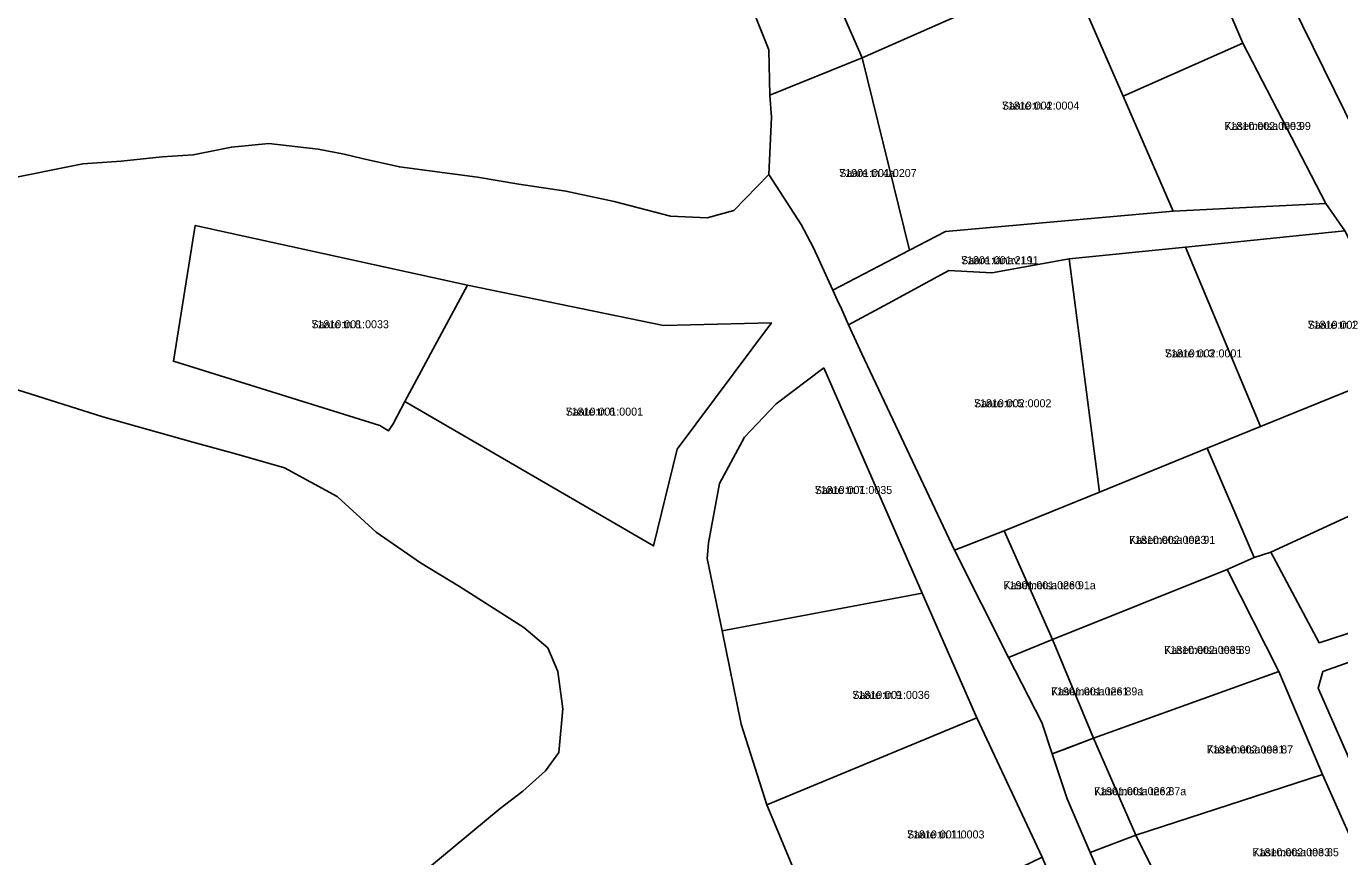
# Model space of a CAD drawing. Extents: x 529768 to 552006, y 6562269 to 6580975.
# Drawn here: x 537630.1 to 537876.3, y 6567349.9 to 6567505.6 of the extents above; entities that cross this region are included whole.
import ezdxf

# ---------------------------------------------------------------- set-up
doc = ezdxf.new("R2010")
doc.units = 0
for name, color, linetype in [('L_AADRESS', 7, 'Continuous'), ('PIIR', 7, 'Continuous'), ('TUNNUS', 7, 'Continuous')]:
    doc.layers.add(name, color=color, linetype=linetype)

msp = doc.modelspace()

# ---------------------------------------------------------------- linework, layer by layer
at = {"layer": 'PIIR'}
for points in [[(537798.54, 6567557.54), (537802.17, 6567549.01), (537809.82, 6567552.1), (537822.77, 6567522.3), (537825.35, 6567516.34), (537806.21, 6567508.25), (537786.78, 6567499.68), (537767.69, 6567543.41)], [(537769.48, 6567492.72), (537769.31, 6567501.21), (537766.81, 6567507.44), (537763.18, 6567514.29), (537758.92, 6567522.05), (537751.47, 6567535.36), (537767.69, 6567543.41), (537786.78, 6567499.68)], [(537872.4, 6567518.04), (537882.48, 6567541.11), (537939.04, 6567528.22), (537959.43, 6567469.61), (537944.31, 6567465.47), (537897.72, 6567452.1), (537885.27, 6567473.37), (537867.28, 6567509.8)], [(537845, 6567532.02), (537855.3, 6567509), (537858.12, 6567502.42), (537835.7, 6567492.5), (537825.35, 6567516.34), (537822.77, 6567522.3)], [(537806.21, 6567508.25), (537825.35, 6567516.34), (537835.7, 6567492.5), (537845.06, 6567470.95), (537802.38, 6567467.11), (537795.67, 6567463.63), (537786.78, 6567499.68)], [(537835.7, 6567492.5), (537858.12, 6567502.42), (537873.7, 6567472.36), (537845.06, 6567470.95)], [(537781.3, 6567456.11), (537777.68, 6567464.06), (537775.34, 6567468.41), (537769.31, 6567477.79), (537769.79, 6567488.59), (537769.48, 6567492.72), (537786.78, 6567499.68), (537795.67, 6567463.63)], [(537784.25, 6567449.63), (537783.81, 6567450.6), (537782.97, 6567452.47), (537782.12, 6567454.32), (537781.3, 6567456.11), (537795.67, 6567463.63), (537802.38, 6567467.11), (537845.06, 6567470.95), (537873.7, 6567472.36), (537877.25, 6567467.22), (537847.4, 6567464.17), (537825.6, 6567461.99), (537811.07, 6567459.4), (537803.01, 6567459.79), (537791.67, 6567453.64)], [(537712.84, 6567457.03), (537701.05, 6567435.27), (537698.89, 6567431.05), (537698.01, 6567429.71), (537696.39, 6567430.71), (537657.69, 6567442.78), (537661.8, 6567468.25)], [(537661.8, 6567468.25), (537657.69, 6567442.78), (537696.39, 6567430.71), (537698.01, 6567429.71), (537698.89, 6567431.05), (537701.05, 6567435.27), (537747.7, 6567408.14), (537752.09, 6567426.3), (537769.77, 6567450.02), (537749.52, 6567449.52), (537712.84, 6567457.03)], [(537877.25, 6567467.22), (537890.24, 6567442.27), (537861.45, 6567430.54), (537847.4, 6567464.17)], [(537847.4, 6567464.17), (537861.45, 6567430.54), (537851.43, 6567426.46), (537831.26, 6567418.23), (537825.6, 6567461.99)], [(537791.67, 6567453.64), (537803.01, 6567459.79), (537811.07, 6567459.4), (537825.6, 6567461.99), (537831.26, 6567418.23), (537813.37, 6567410.96), (537804.09, 6567407.33), (537786.75, 6567444.17), (537784.25, 6567449.63)], [(537749.52, 6567449.52), (537769.77, 6567450.02), (537752.09, 6567426.3), (537747.7, 6567408.14), (537701.05, 6567435.27), (537712.84, 6567457.03)], [(537779.57, 6567441.53), (537798.06, 6567399.32), (537760.54, 6567392.24), (537757.76, 6567405.8), (537757.98, 6567408.72), (537760.05, 6567419.87), (537764.72, 6567428.52), (537770.69, 6567434.81)], [(537779.57, 6567441.53), (537770.69, 6567434.81), (537764.72, 6567428.52), (537760.05, 6567419.87), (537757.98, 6567408.72), (537757.76, 6567405.8), (537760.54, 6567392.24), (537764.13, 6567374.73), (537768.91, 6567359.61), (537781, 6567330.64), (537792.65, 6567304.01), (537805.22, 6567276.68), (537821, 6567240.45), (537822.49, 6567237.53), (537851.52, 6567248.43), (537854.89, 6567253.96), (537854.48, 6567267.98), (537842.1, 6567289.36), (537845.43, 6567291.37), (537832.59, 6567320.98), (537820.5, 6567349.78), (537808.28, 6567375.94), (537798.06, 6567399.32)], [(537851.43, 6567426.46), (537861.45, 6567430.54), (537890.24, 6567442.27), (537900.61, 6567424.2), (537863.37, 6567407.01), (537860.24, 6567405.95)], [(537851.43, 6567426.46), (537860.24, 6567405.95), (537855.17, 6567403.73), (537822.47, 6567390.62), (537813.37, 6567410.96), (537831.26, 6567418.23)], [(537863.37, 6567407.01), (537900.61, 6567424.2), (537912.04, 6567402.87), (537872.45, 6567390)], [(537804.09, 6567407.33), (537813.37, 6567410.96), (537822.47, 6567390.62), (537814.23, 6567387.25)], [(537855.17, 6567403.73), (537864.88, 6567384.57), (537830.14, 6567372.08), (537822.47, 6567390.62)], [(537798.06, 6567399.32), (537808.28, 6567375.94), (537768.91, 6567359.61), (537764.13, 6567374.73), (537760.54, 6567392.24)], [(537873.09, 6567384.57), (537914.21, 6567399.17), (537924.42, 6567380.29), (537879.71, 6567364.56), (537872.27, 6567381.48)], [(537820.43, 6567375.01), (537814.23, 6567387.25), (537822.47, 6567390.62), (537830.14, 6567372.08), (537822.38, 6567369.14)], [(537864.88, 6567384.57), (537873.03, 6567365.29), (537838.09, 6567353.89), (537830.14, 6567372.08)], [(537820.5, 6567349.78), (537781, 6567330.64), (537768.91, 6567359.61), (537808.28, 6567375.94)], [(537822.38, 6567369.14), (537824.45, 6567369.93), (537830.14, 6567372.08), (537838.09, 6567353.89), (537829.52, 6567350.66), (537825.18, 6567360.74)], [(537873.03, 6567365.29), (537881.62, 6567346.03), (537847.69, 6567334.61), (537838.09, 6567353.89)], [(537834.6, 6567338.85), (537829.52, 6567350.66), (537838.09, 6567353.89), (537847.69, 6567334.61), (537838.42, 6567331.33)]]:
    msp.add_lwpolyline(points, close=True, dxfattribs=at)
for points in [[(537867.28, 6567509.8), (537885.27, 6567473.37), (537897.72, 6567452.1), (537931.9, 6567393.33), (537941.85, 6567375.7), (537952.13, 6567357.49), (537960.9, 6567341.94), (537968.08, 6567338.13), (537969.71, 6567332.41), (537967.19, 6567328.02), (537968.16, 6567326.16), (538001.41, 6567260.89), (538017.38, 6567228.01), (538018.21, 6567228.37), (538042.23, 6567182.07), (538051.25, 6567168.5), (538088.38, 6567124.5), (538113.69, 6567097), (538118.69, 6567092.24), (538205.94, 6567024.11)], [(537766.81, 6567507.44), (537769.31, 6567501.21), (537769.48, 6567492.72), (537769.79, 6567488.59), (537769.31, 6567477.79), (537762.73, 6567471.05), (537757.75, 6567469.69), (537750.87, 6567469.98), (537740.31, 6567472.76), (537731.26, 6567474.7), (537722.46, 6567476.01), (537714.72, 6567477.31), (537700.05, 6567479.24), (537693.1, 6567480.79), (537689.68, 6567481.65), (537684.8, 6567482.55), (537675.6, 6567483.66), (537668.56, 6567482.97), (537661.43, 6567481.49), (537655.56, 6567481.11), (537647.92, 6567480.31), (537640.75, 6567479.84), (537625.48, 6567476.78)], [(537877.25, 6567467.22), (537873.7, 6567472.36), (537858.12, 6567502.42), (537855.3, 6567509)], [(537625.48, 6567476.78), (537640.75, 6567479.84), (537647.92, 6567480.31), (537655.56, 6567481.11), (537661.43, 6567481.49), (537668.56, 6567482.97), (537675.6, 6567483.66), (537684.8, 6567482.55), (537689.68, 6567481.65), (537693.1, 6567480.79), (537700.05, 6567479.24), (537714.72, 6567477.31), (537722.46, 6567476.01), (537731.26, 6567474.7), (537740.31, 6567472.76), (537750.87, 6567469.98), (537757.75, 6567469.69), (537762.73, 6567471.05), (537769.31, 6567477.79), (537775.34, 6567468.41), (537777.68, 6567464.06), (537781.3, 6567456.11), (537782.12, 6567454.32), (537782.97, 6567452.47), (537783.81, 6567450.6), (537784.25, 6567449.63), (537786.75, 6567444.17), (537804.09, 6567407.33), (537814.23, 6567387.25), (537820.43, 6567375.01), (537822.38, 6567369.14), (537825.18, 6567360.74), (537829.52, 6567350.66), (537834.6, 6567338.85)], [(537627.29, 6567437.78), (537644.47, 6567432.37), (537661.34, 6567427.59), (537669.61, 6567425.36), (537678.52, 6567422.81), (537688.39, 6567417.4), (537695.71, 6567410.71), (537703.98, 6567404.98), (537711.3, 6567400.53), (537723.4, 6567392.88), (537727.85, 6567389.06), (537729.76, 6567384.61), (537730.71, 6567377.61), (537729.93, 6567369.41), (537727.43, 6567365.95), (537723.17, 6567362.15), (537718.93, 6567358.92), (537702.43, 6567345.21), (537680.18, 6567326.48), (537658.23, 6567309.19), (537628.46, 6567283.1)], [(537628.46, 6567283.1), (537658.23, 6567309.19), (537680.18, 6567326.48), (537702.43, 6567345.21), (537718.93, 6567358.92), (537723.17, 6567362.15), (537727.43, 6567365.95), (537729.93, 6567369.41), (537730.71, 6567377.61), (537729.76, 6567384.61), (537727.85, 6567389.06), (537723.4, 6567392.88), (537711.3, 6567400.53), (537703.98, 6567404.98), (537695.71, 6567410.71), (537688.39, 6567417.4), (537678.52, 6567422.81), (537669.61, 6567425.36), (537661.34, 6567427.59), (537644.47, 6567432.37), (537627.29, 6567437.78)], [(537881.62, 6567346.03), (537873.03, 6567365.29), (537864.88, 6567384.57), (537855.17, 6567403.73), (537860.24, 6567405.95), (537863.37, 6567407.01), (537872.45, 6567390), (537912.04, 6567402.87)], [(537914.21, 6567399.17), (537873.09, 6567384.57), (537872.27, 6567381.48), (537879.71, 6567364.56)]]:
    msp.add_lwpolyline(points, dxfattribs=at)

# ---------------------------------------------------------------- texts
at = {"layer": 'L_AADRESS'}
for s, p in [('Saare tn 4', (537812.98, 6567489.99)), ('Kasemetsa tee 99', (537854.7, 6567486.17)), ('Saare tn 4a', (537782.49, 6567477.34)), ('Saare tänav L1', (537805.33, 6567460.99)), ('Saare tn 8', (537683.58, 6567448.98)), ('Saare tn 1', (537870.29, 6567448.88)), ('Saare tn 3', (537843.53, 6567443.51)), ('Saare tn 5', (537807.75, 6567434.16)), ('Saare tn 6', (537731.22, 6567432.59)), ('Saare tn 7', (537777.91, 6567417.9)), ('Kasemetsa tee 91', (537836.79, 6567408.54)), ('Kasemetsa tee 91a', (537813.28, 6567400.03)), ('Kasemetsa tee 89', (537843.39, 6567387.9)), ('Kasemetsa tee 89a', (537822.18, 6567380.12)), ('Saare tn 9', (537784.95, 6567379.46)), ('Kasemetsa tee 87', (537851.38, 6567369.23)), ('Kasemetsa tee 87a', (537830.24, 6567361.4)), ('Saare tn 11', (537795.2, 6567353.29)), ('Kasemetsa tee 85', (537859.96, 6567349.95))]:
    msp.add_text(s, height=1.5, dxfattribs=at).set_placement(p)
at = {"layer": 'TUNNUS'}
for s, p in [('71810:002:0004', (537812.98, 6567489.99)), ('71810:002:0003', (537854.7, 6567486.17)), ('71901:001:0207', (537782.49, 6567477.34)), ('71801:001:2191', (537805.33, 6567460.99)), ('71810:001:0033', (537683.58, 6567448.98)), ('71810:002:0010', (537870.29, 6567448.88)), ('71810:002:0001', (537843.53, 6567443.51)), ('71810:002:0002', (537807.75, 6567434.16)), ('71810:001:0001', (537731.22, 6567432.59)), ('71810:001:0035', (537777.91, 6567417.9)), ('71810:002:0023', (537836.79, 6567408.54)), ('71901:001:0260', (537813.28, 6567400.03)), ('71810:002:0035', (537843.39, 6567387.9)), ('71901:001:0261', (537822.18, 6567380.12)), ('71810:001:0036', (537784.95, 6567379.46)), ('71810:002:0031', (537851.38, 6567369.23)), ('71901:001:0262', (537830.24, 6567361.4)), ('71810:001:0003', (537795.2, 6567353.29)), ('71810:002:0033', (537859.96, 6567349.95))]:
    msp.add_text(s, height=1.5, dxfattribs=at).set_placement(p)

doc.saveas('drawing.dxf')
